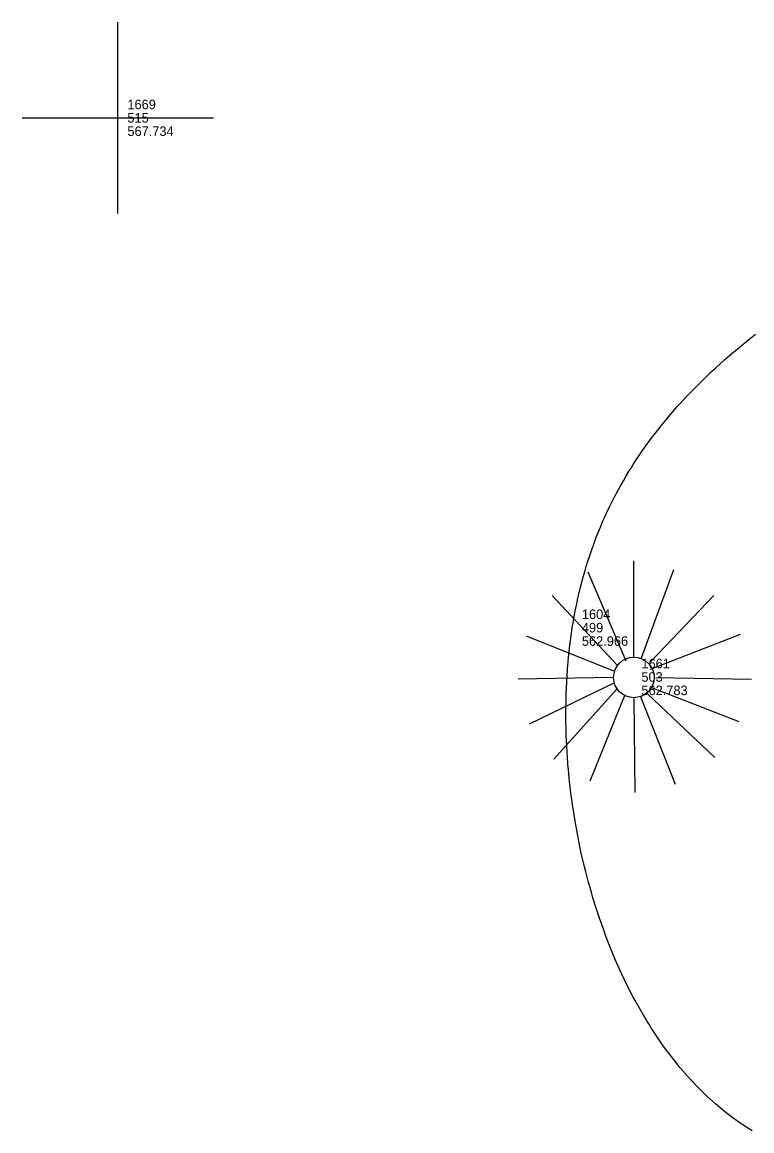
# Model space of a CAD drawing. Extents: x 5447 to 709667, y 4528 to 375505.
# Drawn here: x 707312.93 to 707332.01, y 374469.39 to 374498.37 of the extents above; entities that cross this region are included whole.
import ezdxf

# ---------------------------------------------------------------- set-up
doc = ezdxf.new("R2010")
doc.units = 0
for name, color, linetype in [('SV_NODES_ACTIVE_POINT', 7, 'Continuous'), ('SV_NODES_DESCRIPTION', 7, 'Continuous'), ('SV_NODES_ELEVATION', 7, 'Continuous'), ('SV_NODES_PT_NUMBER', 7, 'Continuous'), ('SV_SURF_SPOT', 7, 'Continuous'), ('SV_TREE_TREEVEG', 7, 'Continuous')]:
    doc.layers.add(name, color=color, linetype=linetype)

msp = doc.modelspace()

# ---------------------------------------------------------------- linework, layer by layer
at = {"layer": 'SV_NODES_ACTIVE_POINT'}
msp.add_line((707327.314, 374482.542), (707327.314, 374482.542), dxfattribs=at)
at = {"layer": 'SV_SURF_SPOT'}
for p, q in [((707315.435, 374493.369), (707315.435, 374498.371)), ((707312.934, 374495.87), (707317.936, 374495.87)), ((707315.435, 374495.87), (707315.435, 374495.87))]:
    msp.add_line(p, q, dxfattribs=at)
at = {"layer": 'SV_TREE_TREEVEG'}
for p, q in [((707328.924, 374481.77), (707328.924, 374484.292)), ((707327.724, 374484.003), (707328.709, 374481.672)), ((707329.957, 374484.05), (707329.116, 374481.744)), ((707326.785, 374483.379), (707328.492, 374481.552)), ((707329.358, 374481.65), (707331.015, 374483.379)), ((707328.398, 374481.407), (707326.114, 374482.321)), ((707329.358, 374481.458), (707331.711, 374482.368)), ((707328.372, 374481.24), (707325.897, 374481.193)), ((707328.42, 374481.096), (707326.187, 374480.015)), ((707329.38, 374480.976), (707331.664, 374480.088)), ((707329.5, 374481.24), (707331.998, 374481.193)), ((707328.467, 374480.929), (707326.835, 374479.102)), ((707328.684, 374480.784), (707327.771, 374478.525)), ((707328.924, 374480.689), (707328.949, 374478.236)), ((707329.09, 374480.759), (707330.004, 374478.453)), ((707329.283, 374480.809), (707331.037, 374479.149))]:
    msp.add_line(p, q, dxfattribs=at)
msp.add_lwpolyline([(707332.014, 374469.388), (707331.875, 374469.476), (707331.783, 374469.536), (707331.603, 374469.661), (707331.514, 374469.726), (707331.339, 374469.86), (707331.167, 374469.999), (707331.054, 374470.096), (707330.98, 374470.161), (707330.834, 374470.296), (707330.753, 374470.373), (707330.593, 374470.532), (707330.437, 374470.696), (707330.335, 374470.808), (707330.268, 374470.884), (707330.136, 374471.039), (707329.99, 374471.217), (707329.895, 374471.339), (707329.833, 374471.421), (707329.71, 374471.588), (707329.62, 374471.715), (707329.56, 374471.801), (707329.444, 374471.976), (707329.387, 374472.064), (707329.312, 374472.183), (707329.274, 374472.243), (707329.165, 374472.425), (707329.094, 374472.547), (707328.955, 374472.797), (707328.898, 374472.903), (707328.786, 374473.119), (707328.678, 374473.338), (707328.608, 374473.486), (707328.473, 374473.785), (707328.376, 374474.012), (707328.313, 374474.165), (707328.193, 374474.475), (707328.135, 374474.631), (707328.024, 374474.946), (707327.92, 374475.265), (707327.854, 374475.479), (707327.812, 374475.623), (707327.731, 374475.912), (707327.667, 374476.157), (707327.626, 374476.321), (707327.549, 374476.651), (707327.514, 374476.817), (707327.447, 374477.149), (707327.387, 374477.483), (707327.351, 374477.706), (707327.328, 374477.854), (707327.3, 374478.053), (707327.287, 374478.152), (707327.259, 374478.375), (707327.243, 374478.524), (707327.223, 374478.722), (707327.213, 374478.821), (707327.201, 374478.97), (707327.186, 374479.168), (707327.179, 374479.267), (707327.168, 374479.464), (707327.157, 374479.727), (707327.152, 374479.858), (707327.147, 374480.151), (707327.146, 374480.37), (707327.15, 374480.661), (707327.154, 374480.806), (707327.168, 374481.129), (707327.176, 374481.272), (707327.189, 374481.461), (707327.197, 374481.555), (707327.216, 374481.766), (707327.25, 374482.08), (707327.291, 374482.389), (707327.314, 374482.542), (707327.342, 374482.714), (707327.383, 374482.94), (707327.405, 374483.052), (707327.428, 374483.164), (707327.46, 374483.312), (707327.477, 374483.385), (707327.53, 374483.604), (707327.606, 374483.893), (707327.647, 374484.035), (707327.678, 374484.141), (707327.722, 374484.282), (707327.745, 374484.352), (707327.815, 374484.56), (707327.864, 374484.698), (707327.932, 374484.88), (707327.967, 374484.971), (707328.05, 374485.172), (707328.106, 374485.306), (707328.185, 374485.482), (707328.226, 374485.57), (707328.288, 374485.7), (707328.373, 374485.873), (707328.417, 374485.959), (707328.554, 374486.214), (707328.649, 374486.382), (707328.714, 374486.493), (707328.803, 374486.641), (707328.848, 374486.714), (707328.907, 374486.806), (707328.986, 374486.929), (707329.026, 374486.99), (707329.15, 374487.171), (707329.235, 374487.291), (707329.35, 374487.45), (707329.409, 374487.529), (707329.545, 374487.705), (707329.638, 374487.822), (707329.764, 374487.977), (707329.828, 374488.053), (707329.926, 374488.168), (707330.059, 374488.32), (707330.127, 374488.395), (707330.336, 374488.62), (707330.479, 374488.769), (707330.576, 374488.867), (707330.707, 374488.997), (707330.774, 374489.062), (707330.945, 374489.226), (707331.062, 374489.334), (707331.301, 374489.548), (707331.423, 374489.655), (707331.672, 374489.867), (707331.929, 374490.076), (707332.104, 374490.215)], dxfattribs=at)
msp.add_circle((707328.924, 374481.24), 0.53, dxfattribs=at)

# ---------------------------------------------------------------- texts
at = {"layer": 'SV_NODES_DESCRIPTION'}
for s, p in [('515', (707315.685, 374495.745)), ('499', (707327.564, 374482.417)), ('503', (707329.12, 374481.128))]:
    msp.add_text(s, height=0.25, dxfattribs=at).set_placement(p)
at = {"layer": 'SV_NODES_ELEVATION'}
for s, p in [('567.734', (707315.685, 374495.395)), ('562.966', (707327.564, 374482.067)), ('562.783', (707329.12, 374480.778))]:
    msp.add_text(s, height=0.25, dxfattribs=at).set_placement(p)
at = {"layer": 'SV_NODES_PT_NUMBER'}
for s, p in [('1669', (707315.685, 374496.095)), ('1604', (707327.564, 374482.767)), ('1661', (707329.12, 374481.478))]:
    msp.add_text(s, height=0.25, dxfattribs=at).set_placement(p)

doc.saveas('drawing.dxf')
